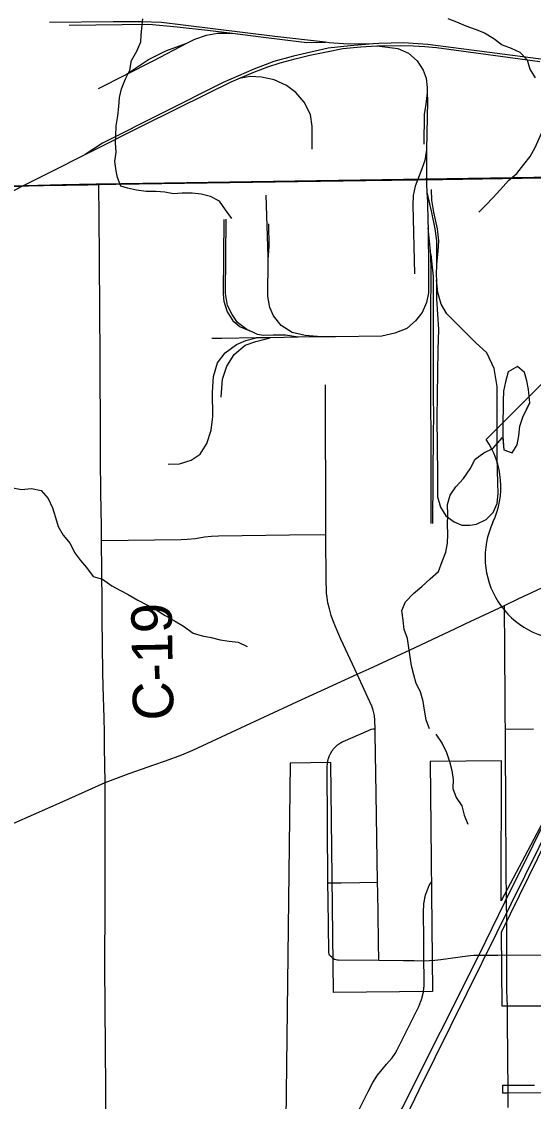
# Model space of a CAD drawing. Extents: x 0 to 34, y 0 to 22.
# Drawn here: x 3.818 to 4.177, y 14.974 to 15.73 of the extents above; entities that cross this region are included whole.
import ezdxf

# ---------------------------------------------------------------- set-up
doc = ezdxf.new("R2010")
doc.units = 0
for name, color, linetype in [('GM_X_City_Street', 7, 'Continuous'), ('GM_X_Corporation', 7, 'Continuous'), ('GM_X_County_Road', 7, 'Continuous'), ('GM_X_County_Road_Text', 7, 'Continuous'), ('GM_X_Minor_Lake', 7, 'Continuous'), ('GM_X_Minor_River', 7, 'Continuous'), ('GM_X_Rail_Line', 7, 'Continuous'), ('GM_X_Rail_Line_Text', 7, 'Continuous'), ('GM_X_Township_Road', 7, 'Continuous'), ('GM_X_US_Route', 7, 'Continuous'), ('GM_X_US_Shield', 7, 'Continuous')]:
    doc.layers.add(name, color=color, linetype=linetype)

msp = doc.modelspace()

# ---------------------------------------------------------------- linework, layer by layer
at = {"layer": 'GM_X_City_Street'}
for points in [[(4.05357, 15.27295), (4.04224, 15.29748), (4.03937, 15.30396), (4.03704, 15.30949), (4.03543, 15.31403), (4.03421, 15.31866), (4.03316, 15.32292), (4.0326, 15.32661), (4.03222, 15.32973), (4.03203, 15.33275), (4.03184, 15.33701), (4.03171, 15.37076), (4.03138, 15.47544)], [(3.87453, 15.36646), (3.93025, 15.36716), (3.93446, 15.36745), (3.94024, 15.36803), (3.94668, 15.3691), (3.95147, 15.36952), (3.95642, 15.36968), (4.00612, 15.37043), (4.03171, 15.37076)], [(4.06879, 15.07258), (4.06863, 15.0847), (4.06826, 15.10566), (4.06811, 15.11968), (4.06795, 15.12726), (4.06695, 15.18926), (4.0662, 15.23103), (4.06614, 15.23466), (4.06603, 15.24051), (4.06565, 15.24404), (4.06479, 15.24759), (4.06383, 15.25057), (4.0586, 15.26205), (4.05357, 15.27295)], [(4.03576, 15.07458), (4.03482, 15.07531), (4.03425, 15.07604), (4.03393, 15.07672), (4.03377, 15.07761), (4.03372, 15.07839), (4.03334, 15.11477), (4.03312, 15.12668), (4.03258, 15.20815), (4.03272, 15.21019), (4.03276, 15.21052), (4.03281, 15.21086), (4.03286, 15.21119), (4.03292, 15.21152), (4.03298, 15.21185), (4.03306, 15.21218), (4.03313, 15.21251), (4.03321, 15.21283), (4.0333, 15.21316), (4.03339, 15.21348), (4.03349, 15.21381), (4.03359, 15.21413), (4.0337, 15.21445), (4.03381, 15.21476), (4.03393, 15.21508), (4.03405, 15.21539), (4.03418, 15.2157), (4.03431, 15.21601), (4.03445, 15.21631), (4.0346, 15.21662), (4.03475, 15.21692), (4.0349, 15.21722), (4.03505, 15.21751), (4.03522, 15.2178), (4.03538, 15.21809), (4.03555, 15.21837), (4.03573, 15.21866), (4.03591, 15.21894), (4.03609, 15.21921), (4.03628, 15.21949), (4.03648, 15.21975), (4.03667, 15.22002), (4.03688, 15.22028), (4.03708, 15.22054), (4.03729, 15.22079), (4.03751, 15.22104), (4.03773, 15.22129), (4.03795, 15.22153), (4.03817, 15.22177), (4.0384, 15.222), (4.03864, 15.22223), (4.03887, 15.22246), (4.03911, 15.22267), (4.03936, 15.22289), (4.03961, 15.2231), (4.03986, 15.22331), (4.04011, 15.22351), (4.04037, 15.22371), (4.04063, 15.2239), (4.0409, 15.22408), (4.04116, 15.22427), (4.04143, 15.22444), (4.04171, 15.22462), (4.04198, 15.22478), (4.04226, 15.22495), (4.04255, 15.2251), (4.04283, 15.22525), (4.04312, 15.2254), (4.04341, 15.22554), (4.0437, 15.22568), (4.06155, 15.23352), (4.06337, 15.23427), (4.06488, 15.2346), (4.06614, 15.23466)], [(4.15747, 15.23435), (4.17726, 15.23467)], [(4.03312, 15.12668), (4.04235, 15.12679), (4.05559, 15.12705), (4.06795, 15.12726)], [(4.03576, 15.07458), (4.03621, 15.07423), (4.03696, 15.07374), (4.03769, 15.07338), (4.03868, 15.07301), (4.03952, 15.07291), (4.04035, 15.07286), (4.06879, 15.07258)], [(4.15851, 15.07624), (4.1851, 15.07617)]]:
    msp.add_lwpolyline(points, dxfattribs=at)
at = {"layer": 'GM_X_Corporation'}
for points in [[(4.20455, 15.20857), (4.1546, 15.11419), (4.15477, 15.2123), (4.10468, 15.21174), (4.10648, 15.05068), (4.03695, 15.0499), (4.03514, 15.21097), (4.00669, 15.21065), (4.00204, 14.82613)], [(4.1832, 15.04041), (4.15802, 15.0404), (4.15513, 15.0404), (4.1548, 15.09227), (4.21186, 15.20859)], [(4.18319, 14.97957), (4.15847, 14.97939), (4.15563, 14.97938), (4.15558, 14.9851), (4.15843, 14.9851), (4.17777, 14.9851)]]:
    msp.add_lwpolyline(points, dxfattribs=at)
at = {"layer": 'GM_X_County_Road'}
for p, q in [((3.81126, 15.61457), (3.82944, 15.61506)), ((3.82944, 15.61506), (3.83394, 15.61514)), ((3.87695, 15.15751), (3.87695, 15.19692)), ((4.15935, 14.98107), (4.15931, 14.9868))]:
    msp.add_line(p, q, dxfattribs=at)
for points in [[(3.87266, 15.61578), (3.89673, 15.61625), (3.90085, 15.61633), (4.05971, 15.61867), (4.11369, 15.61946)], [(4.11369, 15.61946), (4.18317, 15.62047), (4.19828, 15.62069), (4.29901, 15.62195)], [(3.83394, 15.61514), (3.86511, 15.61572), (3.87266, 15.61578)], [(3.87282, 15.59576), (3.87271, 15.61311), (3.87266, 15.61578)], [(3.87387, 15.42402), (3.87382, 15.4283), (3.87389, 15.44562), (3.8736, 15.48571), (3.87347, 15.50326), (3.87335, 15.51919), (3.87328, 15.52904), (3.87304, 15.56171), (3.87282, 15.59576)], [(3.87412, 15.40062), (3.87387, 15.42354), (3.87387, 15.42402)], [(3.87438, 15.37628), (3.87412, 15.40012), (3.87412, 15.40062)], [(3.87471, 15.34468), (3.87453, 15.36646), (3.87438, 15.37628)], [(3.875, 15.31148), (3.8749, 15.32331), (3.87471, 15.34468)], [(4.15756, 15.2154), (4.15746, 15.23094), (4.15747, 15.23435), (4.15738, 15.24278), (4.15726, 15.25445), (4.1572, 15.26629), (4.15713, 15.27816), (4.15707, 15.28972), (4.1569, 15.32111)], [(3.87695, 15.19692), (3.87662, 15.22173), (3.87651, 15.23208), (3.8764, 15.24232), (3.87573, 15.26436), (3.8754, 15.27426), (3.875, 15.31148)], [(4.15826, 15.11411), (4.15826, 15.11455), (4.15812, 15.13598), (4.15797, 15.15256), (4.15788, 15.16526), (4.15782, 15.17489), (4.15774, 15.18743), (4.15767, 15.19786), (4.15762, 15.20572), (4.15756, 15.2154)], [(3.87885, 14.76779), (3.87807, 14.90556), (3.87796, 14.9256), (3.87684, 15.06838), (3.87695, 15.11211), (3.87695, 15.15751)], [(4.15841, 15.09381), (4.15836, 15.10324), (4.15826, 15.11101), (4.15826, 15.11411)], [(4.15885, 15.04211), (4.15876, 15.04415), (4.15856, 15.05291), (4.15851, 15.07624), (4.15841, 15.09381)], [(4.15931, 14.9868), (4.15921, 14.9983), (4.15915, 15.0053), (4.15912, 15.00983), (4.15908, 15.01426), (4.15903, 15.02097), (4.15892, 15.03321), (4.15885, 15.04211)], [(4.15945, 14.96951), (4.1594, 14.97583), (4.15935, 14.98107)]]:
    msp.add_lwpolyline(points, dxfattribs=at)
at = {"layer": 'GM_X_Minor_Lake'}
for points in [[(4.17461, 15.46304), (4.17374, 15.47232), (4.17245, 15.47841), (4.17096, 15.48412), (4.16585, 15.48834), (4.15937, 15.48457), (4.15763, 15.47773), (4.15608, 15.47108), (4.15585, 15.46443), (4.15582, 15.45815), (4.1556, 15.4513), (4.15576, 15.44654), (4.15572, 15.43783)], [(4.17463, 15.46288), (4.17374, 15.47232), (4.17245, 15.47841), (4.17096, 15.48412), (4.16585, 15.48834), (4.15937, 15.48457), (4.15763, 15.47773), (4.15608, 15.47108), (4.15585, 15.46443), (4.15582, 15.45815), (4.1556, 15.4513), (4.15576, 15.44654), (4.15573, 15.4397)], [(4.15559, 15.43929), (4.15644, 15.42999), (4.16213, 15.42787), (4.16576, 15.43355), (4.16694, 15.43982), (4.16754, 15.44667), (4.16966, 15.45294), (4.17463, 15.46307)], [(4.15572, 15.43783), (4.15644, 15.42999), (4.16213, 15.42787), (4.16576, 15.43355), (4.16694, 15.43982), (4.16754, 15.44667), (4.16966, 15.45294), (4.17461, 15.46304)]]:
    msp.add_lwpolyline(points, dxfattribs=at)
at = {"layer": 'GM_X_Minor_River'}
for points in [[(3.96576, 15.59194), (3.96137, 15.5982), (3.95716, 15.60409), (3.95088, 15.60749), (3.94441, 15.60917), (3.93795, 15.60991), (3.93111, 15.60989), (3.92504, 15.60929), (3.91876, 15.6106), (3.91269, 15.61096), (3.90585, 15.61094), (3.89901, 15.61186), (3.89273, 15.61336), (3.88798, 15.61467), (3.88567, 15.62075), (3.8847, 15.6255), (3.88391, 15.63197), (3.88483, 15.63844), (3.88423, 15.64528), (3.88458, 15.65004), (3.88474, 15.65689), (3.88585, 15.66393), (3.88658, 15.6704), (3.88712, 15.67687), (3.88842, 15.68296), (3.89123, 15.68982), (3.89443, 15.69592), (3.89554, 15.70277), (3.89931, 15.70925), (3.90194, 15.71572), (3.9023, 15.72048), (3.90265, 15.72543), (3.90338, 15.7319)], [(4.11705, 15.73211), (4.12314, 15.72985), (4.1298, 15.72702), (4.13627, 15.72476), (4.14274, 15.72212), (4.1494, 15.71815)], [(4.1494, 15.71815), (4.15512, 15.71361), (4.1614, 15.71135), (4.16749, 15.70852), (4.17264, 15.70321), (4.17457, 15.69675), (4.1784, 15.69049)], [(4.13896, 15.59657), (4.14406, 15.60154), (4.1486, 15.6065), (4.15408, 15.61241), (4.15974, 15.61871), (4.16542, 15.62368), (4.17033, 15.62997), (4.17486, 15.63551), (4.17825, 15.6418), (4.18107, 15.64808), (4.18408, 15.65475), (4.18727, 15.66161), (4.18895, 15.66808), (4.18856, 15.68445)], [(4.10438, 15.23467), (4.10188, 15.24094), (4.1009, 15.24759), (4.09992, 15.25368), (4.09799, 15.26052), (4.09492, 15.2664), (4.09338, 15.27248), (4.09164, 15.27875), (4.09085, 15.28503), (4.08987, 15.2913), (4.08889, 15.29777), (4.08658, 15.30422), (4.08579, 15.31069), (4.085, 15.31753), (4.08744, 15.32363), (4.09311, 15.32935), (4.09897, 15.33432), (4.10465, 15.33967), (4.1107, 15.34483), (4.11314, 15.35187), (4.11576, 15.35835), (4.11687, 15.36463), (4.11723, 15.37091), (4.11681, 15.37775), (4.11716, 15.3846), (4.11694, 15.39164), (4.11881, 15.3983), (4.12277, 15.40421), (4.12806, 15.40994), (4.13278, 15.41661), (4.13635, 15.42348), (4.14241, 15.42787), (4.14866, 15.43094), (4.15539, 15.43869)], [(3.81243, 15.40346), (3.81851, 15.40215), (3.82535, 15.40293), (3.83219, 15.40144), (3.83716, 15.39594), (3.84023, 15.38948), (3.84216, 15.38264), (3.84409, 15.37637), (3.84753, 15.3703), (3.8525, 15.36442), (3.85557, 15.35816), (3.85977, 15.35246), (3.86397, 15.34753), (3.86875, 15.34128), (3.87522, 15.3394), (3.8817, 15.33467), (3.88741, 15.33183), (3.89312, 15.32881), (3.89998, 15.32465), (3.90664, 15.32125), (3.91273, 15.31785), (3.91902, 15.31407), (3.92569, 15.31029), (3.93197, 15.30651), (3.93864, 15.30159), (3.94492, 15.29971), (3.95138, 15.29859), (3.95765, 15.2969), (3.96393, 15.29598), (3.9702, 15.29524), (3.97648, 15.29222)], [(4.10869, 15.2308), (4.11314, 15.22444), (4.11627, 15.21812), (4.11825, 15.21181), (4.11985, 15.20532), (4.12088, 15.19923), (4.12058, 15.19277), (4.12295, 15.18646), (4.12684, 15.18069), (4.12863, 15.1742), (4.13118, 15.16788)]]:
    msp.add_lwpolyline(points, dxfattribs=at)
at = {"layer": 'GM_X_Rail_Line'}
for p, q in [((3.87239, 15.68303), (3.89137, 15.69267)), ((4.10512, 15.5668), (4.10325, 15.5856)), ((3.99256, 15.50852), (3.98279, 15.50836)), ((4.01228, 15.50883), (3.99256, 15.50852)), ((4.02856, 15.50909), (4.01228, 15.50883))]:
    msp.add_line(p, q, dxfattribs=at)
for points in [[(4.03152, 15.71545), (3.99588, 15.71955), (3.93163, 15.72755), (3.91646, 15.7293), (3.90231, 15.72976), (3.88268, 15.72972), (3.83812, 15.72924)], [(3.85181, 15.72738), (3.90772, 15.72822), (3.92745, 15.72641), (3.94868, 15.72396), (3.96615, 15.72179)], [(3.93434, 15.71476), (3.93998, 15.71769), (3.94796, 15.72052), (3.95577, 15.72187), (3.96615, 15.72179)], [(3.96615, 15.72179), (3.98621, 15.7193), (4.01833, 15.71534), (4.03152, 15.71545)], [(3.72869, 15.56942), (3.90394, 15.65744), (3.9488, 15.67967), (3.96539, 15.68781), (3.98132, 15.69459), (3.99113, 15.69818), (3.99968, 15.70101), (4.01015, 15.70395), (4.02051, 15.70653), (4.0321, 15.7089), (4.04358, 15.71113), (4.05627, 15.71224), (4.0675, 15.71295), (4.08409, 15.71315), (4.09304, 15.71305), (4.10103, 15.71255), (4.10922, 15.71179), (4.1816, 15.70213)], [(4.06487, 15.71433), (4.0488, 15.71303), (4.03331, 15.71132), (4.00903, 15.70572), (3.99529, 15.70204), (3.9813, 15.69663), (3.95978, 15.68734), (3.87509, 15.64476), (3.86295, 15.63685)], [(3.89137, 15.69267), (3.90733, 15.70338), (3.91947, 15.70958), (3.93434, 15.71476)], [(3.89137, 15.69267), (3.91105, 15.70266), (3.93434, 15.71476)], [(4.06487, 15.71433), (4.04728, 15.71406), (4.03396, 15.71517), (4.03152, 15.71545)], [(4.22536, 15.69775), (4.19302, 15.70227), (4.10313, 15.71402), (4.08613, 15.71501), (4.06876, 15.71465), (4.06487, 15.71433)], [(4.0675, 15.71295), (4.08218, 15.71114), (4.08946, 15.70786), (4.09555, 15.70252), (4.09996, 15.69606), (4.10186, 15.69042), (4.10265, 15.68385), (4.10275, 15.67996)], [(4.02219, 15.64057), (4.02217, 15.65642), (4.02081, 15.66485), (4.01638, 15.67344), (4.01066, 15.68035), (4.00421, 15.68522), (3.99553, 15.68915), (3.98668, 15.69094), (3.97867, 15.69144), (3.97083, 15.69013)], [(4.10275, 15.67996), (4.10161, 15.67225), (4.10064, 15.66483), (4.10032, 15.64416)], [(4.10275, 15.67996), (4.1029, 15.6744), (4.1023, 15.64019)], [(4.1023, 15.64019), (4.10095, 15.63267), (4.09812, 15.62487), (4.09428, 15.61474), (4.09275, 15.60815), (4.09261, 15.60129), (4.09377, 15.55338)], [(4.1023, 15.64019), (4.10218, 15.61581), (4.10246, 15.61058)], [(4.10246, 15.61058), (4.10283, 15.60368), (4.1032, 15.58987), (4.10325, 15.5856)], [(4.10246, 15.61058), (4.10567, 15.59625), (4.10807, 15.58477), (4.10915, 15.57644), (4.10913, 15.56559), (4.10909, 15.56003)], [(4.10556, 15.61247), (4.10561, 15.60487), (4.10706, 15.59644), (4.10956, 15.58488), (4.11055, 15.57635), (4.11013, 15.56921), (4.10909, 15.56003)], [(3.99115, 15.56335), (3.99116, 15.5651), (3.98975, 15.60829)], [(3.98088, 15.5122), (3.97139, 15.51612), (3.96727, 15.51962), (3.96257, 15.52719), (3.96038, 15.53384), (3.95998, 15.5394), (3.96046, 15.5914)], [(3.98088, 15.5122), (3.97624, 15.5143), (3.9697, 15.51917), (3.96612, 15.5248), (3.96282, 15.53117), (3.96128, 15.5395), (3.96186, 15.59169)], [(3.99115, 15.56335), (3.99185, 15.57252), (3.99165, 15.58828)], [(4.10325, 15.5856), (4.10362, 15.55558), (4.10363, 15.53991), (4.10219, 15.53314), (4.09926, 15.52616), (4.09437, 15.52038), (4.08836, 15.51497), (4.07991, 15.51167), (4.0709, 15.50975), (4.03843, 15.50925), (4.02856, 15.50909)], [(4.10538, 15.37845), (4.10533, 15.52324), (4.10539, 15.5555), (4.10512, 15.5668)], [(4.10512, 15.5668), (4.1069, 15.55152), (4.1068, 15.53975), (4.10683, 15.52056), (4.10691, 15.46862), (4.10711, 15.45259), (4.1069, 15.4423), (4.1064, 15.37843)], [(4.02856, 15.50909), (4.01712, 15.51004), (4.00798, 15.51211), (4.00041, 15.51715), (3.99506, 15.52379), (3.99233, 15.5298), (3.99097, 15.53748), (3.99115, 15.56335)], [(4.10909, 15.56003), (4.10904, 15.55243), (4.10908, 15.54919)], [(4.10908, 15.54919), (4.10924, 15.53584), (4.1106, 15.51435), (4.11014, 15.50016), (4.10944, 15.45251), (4.10989, 15.41247), (4.11, 15.39718), (4.11191, 15.38996), (4.11577, 15.38378), (4.12156, 15.37965), (4.12698, 15.37718), (4.13256, 15.37722), (4.13711, 15.37808), (4.14388, 15.38128), (4.14887, 15.38623), (4.15162, 15.39246), (4.15232, 15.39978), (4.15227, 15.40674), (4.15159, 15.4249), (4.15172, 15.47449), (4.14958, 15.48708), (4.14448, 15.49808), (4.13653, 15.50525), (4.11638, 15.52532), (4.11243, 15.53206), (4.11014, 15.5402), (4.10908, 15.54919)], [(4.01228, 15.50883), (4.00334, 15.51041), (3.99469, 15.51025), (3.98809, 15.51002), (3.98389, 15.51083), (3.98088, 15.5122)], [(3.92114, 15.42003), (3.92914, 15.42027), (3.93722, 15.42283), (3.94361, 15.42704), (3.94831, 15.43449), (3.95141, 15.44378), (3.95237, 15.45343), (3.95225, 15.47048), (3.95302, 15.48142), (3.95574, 15.49099), (3.96109, 15.49807), (3.96896, 15.50378), (3.97555, 15.5066), (3.98279, 15.50836)], [(3.98279, 15.50836), (3.95879, 15.50797), (3.95181, 15.50793)], [(3.95832, 15.467), (3.95917, 15.47961), (3.96218, 15.48872), (3.96743, 15.49672), (3.97511, 15.50336), (3.98253, 15.506), (3.99256, 15.50852)], [(3.70769, 14.1), (3.71243, 14.3306), (3.73023, 14.38949), (3.74219, 14.43006), (3.75613, 14.46237), (3.77482, 14.50253), (3.7987, 14.54083), (3.89555, 14.68363), (3.91164, 14.70886), (3.95271, 14.76779), (4.03727, 14.89285), (4.06313, 14.93222), (4.08511, 14.96883), (4.13899, 15.07635), (4.15737, 15.11376), (4.29446, 15.38952)], [(4.00327, 14.79), (4.01769, 14.81843), (4.03298, 14.85192), (4.05287, 14.89238), (4.06588, 14.91735), (4.09709, 14.98169), (4.13044, 15.04928), (4.15171, 15.09223), (4.19103, 15.1716)]]:
    msp.add_lwpolyline(points, dxfattribs=at)
at = {"layer": 'GM_X_Rail_Line_Text'}
for points in [[(3.11906, 15.60565), (3.30823, 15.60755), (3.4013, 15.60851), (3.48021, 15.60936), (3.53436, 15.60998), (3.56071, 15.6104), (3.61401, 15.61125), (3.683, 15.61236), (3.73364, 15.61338), (3.75119, 15.61371), (3.82122, 15.61502), (3.84719, 15.61558), (3.87078, 15.61609), (3.87316, 15.61614), (4.29897, 15.62253), (4.29834, 15.72311), (4.29818, 15.78347)], [(2.1, 14.1), (4.29894, 14.1), (4.29942, 14.35536), (4.30008, 14.70375), (4.3001, 14.71018), (4.30139, 15.38981), (4.29897, 15.62253), (3.87316, 15.61614), (3.87078, 15.61609), (3.84719, 15.61558), (3.82122, 15.61502), (3.75119, 15.61371), (3.73364, 15.61338), (3.683, 15.61236), (3.61401, 15.61125), (3.56071, 15.6104), (3.53436, 15.60998), (3.48021, 15.60936), (3.4013, 15.60851), (3.30823, 15.60755), (3.11906, 15.60565)]]:
    msp.add_lwpolyline(points, dxfattribs=at)
at = {"layer": 'GM_X_Township_Road'}
msp.add_line((4.06879, 15.07258), (4.08617, 15.07237), dxfattribs=at)
for points in [[(4.03702, 14.93208), (4.06133, 14.98055), (4.06457, 14.98701), (4.0678, 14.99201), (4.07103, 14.99609), (4.07426, 14.99986), (4.0781, 15.00424), (4.08026, 15.00732), (4.08164, 15.00971), (4.08318, 15.01301), (4.09652, 15.03958), (4.0968, 15.04018), (4.09708, 15.04078), (4.09735, 15.04139), (4.0976, 15.042), (4.09784, 15.04261), (4.09808, 15.04323), (4.09849, 15.04441), (4.0987, 15.04504), (4.0989, 15.04567), (4.09909, 15.0463), (4.09926, 15.04694), (4.09943, 15.04758), (4.09959, 15.04822), (4.09973, 15.04887), (4.09986, 15.04952), (4.09999, 15.05017), (4.1001, 15.05082), (4.10019, 15.05147), (4.10028, 15.05213), (4.10036, 15.05279), (4.10042, 15.05344), (4.10047, 15.0541), (4.10052, 15.05476), (4.10059, 15.06068), (4.10043, 15.07219), (4.10033, 15.08553), (4.10016, 15.10793), (4.10023, 15.11048), (4.10028, 15.11113), (4.10033, 15.11178), (4.1004, 15.11243), (4.10048, 15.11308), (4.10057, 15.11373), (4.10068, 15.11438), (4.10079, 15.11502), (4.10092, 15.11566), (4.10106, 15.1163), (4.1012, 15.11694), (4.10136, 15.11757), (4.10153, 15.1182), (4.10172, 15.11883), (4.10191, 15.11945), (4.10211, 15.12007), (4.10233, 15.12069), (4.10256, 15.12131), (4.10279, 15.12192), (4.10304, 15.12252), (4.1033, 15.12312), (4.10357, 15.12372), (4.10385, 15.12432), (4.10414, 15.1249), (4.10444, 15.12549), (4.10475, 15.12607), (4.10507, 15.12664), (4.1054, 15.12721)], [(4.08617, 15.07237), (4.09363, 15.07228), (4.10043, 15.07219), (4.10429, 15.07236), (4.10799, 15.07262), (4.11221, 15.07317), (4.13094, 15.07561), (4.13298, 15.07582), (4.13544, 15.07598), (4.14436, 15.07608), (4.15225, 15.07619), (4.15851, 15.07624)]]:
    msp.add_lwpolyline(points, dxfattribs=at)
at = {"layer": 'GM_X_US_Route'}
for points in [[(3.87695, 15.19692), (3.89376, 15.20326), (3.91123, 15.20938), (3.91939, 15.21216), (3.93075, 15.21645), (3.93843, 15.21957), (3.98561, 15.24154), (4.01481, 15.25509), (4.03068, 15.26241), (4.03932, 15.26639), (4.05357, 15.27295), (4.06196, 15.27659), (4.09074, 15.28996), (4.12203, 15.30476), (4.12923, 15.30822), (4.1569, 15.32111), (4.16734, 15.32604), (4.17292, 15.32866), (4.18688, 15.33524)], [(3.7273, 15.12762), (3.74059, 15.13397), (3.774, 15.14982), (3.81102, 15.16755), (3.84687, 15.18352), (3.87695, 15.19692)]]:
    msp.add_lwpolyline(points, dxfattribs=at)
at = {"layer": 'GM_X_US_Shield'}
msp.add_line((4.18508, 15.47838), (4.14388, 15.43718), dxfattribs=at)
for centre, start, end in [((4.09663, 15.4041), 334.54712, 35.00093), ((4.20092, 15.35478), 154.83192, 270.63826)]:
    msp.add_arc(centre, 0.05768, start, end, dxfattribs=at)

# ---------------------------------------------------------------- texts
at = {"layer": 'GM_X_County_Road_Text'}
msp.add_text('C-19', height=0.028409, rotation=91.0286, dxfattribs=at).set_placement((3.92505, 15.24068))

doc.saveas('drawing.dxf')
